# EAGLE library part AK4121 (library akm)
Asynchronous Sample Rate Converter 24-Bit, 96 kHz
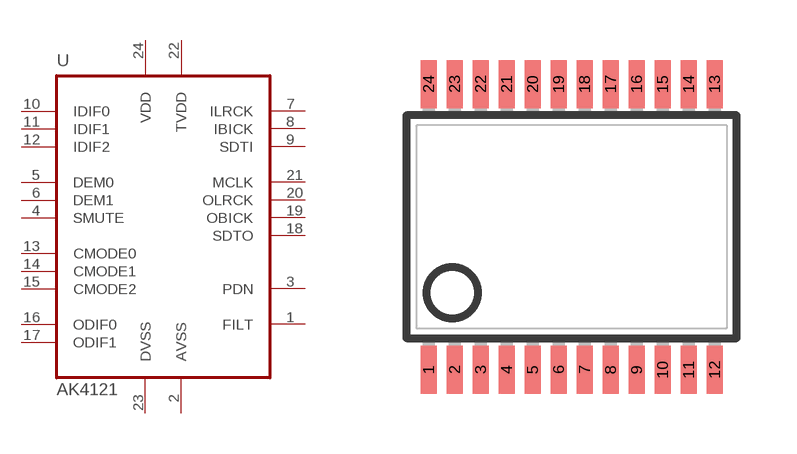
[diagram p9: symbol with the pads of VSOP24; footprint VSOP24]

Designator prefix U

## AK4121  [VSOP24]
1  FILT  pas
2  AVSS  pwr
3  PDN  in
4  SMUTE  in
5  DEM0  in
6  DEM1  in
7  ILRCK  in
8  IBICK  in
9  SDTI  in
10  IDIF0  in
11  IDIF1  in
12  IDIF2  in
13  CMODE0  in
14  CMODE1  in
15  CMODE2  in
16  ODIF0  in
17  ODIF1  in
18  SDTO  out
19  OBICK
20  OLRCK
21  MCLK  in
22  TVDD  pwr
23  DVSS  pwr
24  VDD  pwr

## Footprint VSOP24 (pad centres in mm)
VSOP24 7.8 x 5.6 mm, pitch .65 mm
smd 0.4 x 1.2: 1 -3.575,-3.57; 2 -2.925,-3.57; 3 -2.275,-3.57; 4 -1.625,-3.57; 5 -0.975,-3.57; 6 -0.325,-3.57; 7 0.325,-3.57; 8 0.975,-3.57; 9 1.625,-3.57; 10 2.275,-3.57; 11 2.925,-3.57; 12 3.575,-3.57; 13 3.575,3.57; 14 2.925,3.57; 15 2.275,3.57; 16 1.625,3.57; 17 0.975,3.57; 18 0.325,3.57; 19 -0.325,3.57; 20 -0.975,3.57; 21 -1.625,3.57; 22 -2.275,3.57; 23 -2.925,3.57; 24 -3.575,3.57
